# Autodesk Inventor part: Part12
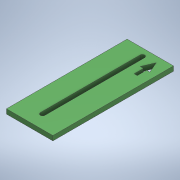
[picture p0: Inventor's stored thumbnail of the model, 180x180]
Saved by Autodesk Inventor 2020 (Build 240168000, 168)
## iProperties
Created: 2019-03
Part Number: Part12
Material: Generic
Document SubType Name: Modeling
Designer: user
Density: 1 g/cm^3
Appearance: Default
Author: user
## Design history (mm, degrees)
sketch "Sketch1"
  geometry: L1 (-419.034, -81.24)-(-319.034, -81.24); L2 (-319.034, -81.24)-(-319.034, 178.76); L3 (-319.034, 178.76)-(-419.034, 178.76); L4 (-419.034, 178.76)-(-419.034, -81.24); 1 further point
  constraints: 8 end point, 2 parallel, 1 horizontal, 1 perpendicular
  dimensions: "d0" = 100 distance of L3.end L2.end; "d1" = 260 distance of L2.end L1.end
extrude "Extrusion1" new body sketch "Sketch1" distance "d2" = 10; taper "d3" = 0 deg
sketch "Sketch2"
  geometry: L1 (-370.395, 163.023)-(-370.395, -51.977); L2 (-375.395, 163.023)-(-375.395, -51.977); L3 (-365.395, -51.977)-(-365.395, 163.023); A1 r 5 centre (-370.395, 163.023) between (-365.395, 163.023) and (-375.395, 163.023); A2 r 5 centre (-370.395, -51.977) between (-375.395, -51.977) and (-365.395, -51.977); 2 further points
  constraints: 8 end point, 4 point on circle, 4 tangent, 2 centre point, 1 midpoint, 1 parallel, 1 vertical
  dimensions: "d4" = 10 diameter of A2; "d7" = 215 distance of L1.start L1.end
extrude "Extrusion2" cut sketch "Sketch2" extent not by distance; stored distance "d5" = 10; taper "d6" = 0 deg
sketch "Sketch3"
  geometry: L1 (-340.046, 141.713)-(-340.046, 121.57); L2 (-340.046, 121.57)-(-346.76, 121.57); L3 (-346.76, 121.57)-(-346.76, 141.713); L4 (-343.403, 166.029)-(-353.837, 141.713); L5 (-343.403, 166.029)-(-332.968, 141.713); L6 (-353.837, 141.713)-(-346.76, 141.713); L7 (-340.046, 141.713)-(-332.968, 141.713); 1 further point
  constraints: 14 end point, 2 horizontal, 1 parallel
extrude "Extrusion3" cut sketch "Sketch3" distance "d8" = 10; taper "d9" = 0 deg
body "Solid1"
